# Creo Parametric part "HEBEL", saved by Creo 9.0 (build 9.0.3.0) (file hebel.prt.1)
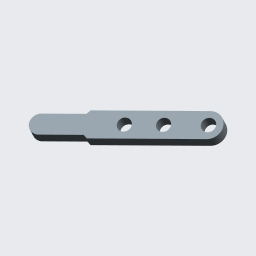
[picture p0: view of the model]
Units: millimeter Kilogram Sec (mmKs); MM, KILOGRAM, SECS
Materials in the file: STAHL

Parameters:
  WERKSTOFF = "Stahl"
  ERSTELLER = "ARINDA"
  BENENNUNG = "XXX"
  TEILETYP = "K"
  PTC_MASTER_MATERIAL = "STAHL"

Other parameters: MASSE

Created from: ARINDA_STARTTEIL.PRT

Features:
  1. coordinate system
  2. datum plane "RECHTS_Y-Z"
  3. datum plane "OBEN_X-Z"
  4. datum plane "VORNE_X-Y"
  5. datum axis
  6. datum axis
  7. datum axis
  8. datum point "PNT0"
  9. extrusion "Profil 1"
  10. hole "Bohrung 1"
  11. pattern "Muster 1"
  12. hole "Bohrung 2"
  13. hole "Bohrung 2 [2]"

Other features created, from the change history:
  coordinate system "CS1"
  hole "Bohrung 2"
  pattern "Muster 1"
  hole "Bohrung 1 [2]"
  hole "Bohrung 1 [3]"

Other named items: A_X, A_Y, A_Z, CS0

Layers: 01_ACHSEN, 01_ACHSEN_STD, 01_EBENEN_STD, 01_KOORDSYS_STD, 01_PUNKTE_STD, VOLUMENGEOMETRIE

Surfaces: 8 plane, 5 cylinder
